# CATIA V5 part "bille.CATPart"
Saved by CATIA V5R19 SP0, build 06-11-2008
Part number: Part2.2
Bounding box of the stored display mesh (mm): x -5 to 5, y -4.999 to 4.999, z -4.999 to 4.999
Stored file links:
  F:\20\bille.CATPart
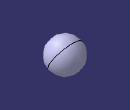
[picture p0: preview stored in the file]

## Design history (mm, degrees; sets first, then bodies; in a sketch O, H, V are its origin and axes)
Body1 (main body)
  Sketch1 on zx-plane, origin (0, 0, 0), H (-1, 0, 0), V (0, 0, 1)
    arc A1 centre (0, 0) radius 5 from (5, 0) to (-5, 0) ccw
    point P1 (5, 0)
    point P2 (-5, 0)
    radius A1 = 5
    coincidence: P1 H, P2 H
  Shaft1: profile Sketch1, axis Sketch1.H, angle 360
  Point1: type Center, Curve face of Shaft1 from Sketch1.A1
